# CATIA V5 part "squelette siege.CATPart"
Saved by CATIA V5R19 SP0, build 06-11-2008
Part number: squelette siege
Publications: "Plan.1", "Plan.2", "Plan.3", "Point.1", "Point.2", "Droite.1", "Plan.4", "longueur du tube", "longeur total du tube", "rayon interieur du tube", "rayon du support"
Bounding box of the stored display mesh (mm): x 0 to 0, y 0 to 0, z 0 to 170
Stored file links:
  I:\yyang\yyang\squelette siege.CATPart
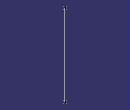
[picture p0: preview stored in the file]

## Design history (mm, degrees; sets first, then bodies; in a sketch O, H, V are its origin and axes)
Parameters
  `longueur du tube` = 150 mm
  `longeur total du tube` = 170 mm
  `rayon interieur du tube` = 10 mm
  `rayon du support` = 15 mm
Body1 (main body)
  Plane1: type Offset, Offset 0, RefPlane xy-plane
  Plane2: type Offset, Offset 0, RefPlane yz-plane
  Plane3: type Offset, Offset 0, RefPlane zx-plane
  Point1: (0, 0, 0)
  Point2: (0, 0, 170 {= `longeur total du tube`})
  Line1: type PtPt, SecondPoint Point1, FirstPoint Point2
  Plane4: type OffsetPt, RefPlane Plane1, RefPoint Point2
